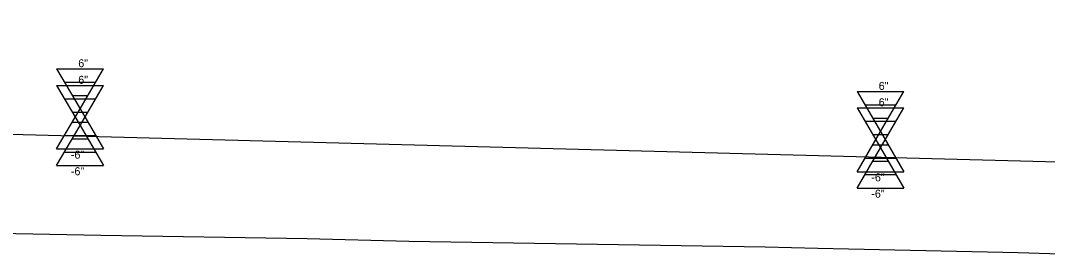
# Model space of a CAD drawing. Extents: x 573468 to 580768, y -57414 to -51768.
# Drawn here: x 574611.5 to 574675.6, y -53062.3 to -53047.5 of the extents above; entities that cross this region are included whole.
import ezdxf

# ---------------------------------------------------------------- set-up
doc = ezdxf.new("R2010")
doc.units = 0
for name, color, linetype in [('Exist Vertical Profile Ground Line', 7, 'Continuous'), ('Pattern 2', 7, 'Continuous'), ('Prop Vertical Profile Grade', 7, 'Continuous'), ('Scratch_Level_0', 7, 'Continuous')]:
    doc.layers.add(name, color=color, linetype=linetype)

msp = doc.modelspace()

# ---------------------------------------------------------------- linework, layer by layer
at = {"layer": 'Exist Vertical Profile Ground Line'}
msp.add_lwpolyline([(574543.255, -53059.77), (574554.026, -53059.906), (574560.775, -53060.086), (574583.28, -53060.379), (574588.793, -53060.537), (574611.208, -53060.826), (574616.517, -53060.941), (574629.403, -53061.136), (574635.759, -53061.316), (574658.007, -53061.658), (574661.307, -53061.757), (574673.813, -53062.023), (574681.74, -53062.264)], dxfattribs=at)
at = {"layer": 'Pattern 2'}
for p, q in [((574613.748, -53051.594), (574616.68, -53051.594)), ((574613.748, -53051.594), (574615.214, -53054.094)), ((574615.214, -53054.094), (574616.68, -53051.594)), ((574614.236, -53052.428), (574616.191, -53052.428)), ((574663.748, -53052.994), (574666.68, -53052.994)), ((574663.748, -53052.994), (574665.214, -53055.494)), ((574665.214, -53055.494), (574666.68, -53052.994)), ((574614.725, -53053.261), (574615.703, -53053.261)), ((574664.236, -53053.828), (574666.191, -53053.828)), ((574613.748, -53056.594), (574615.214, -53054.094)), ((574615.214, -53054.094), (574616.68, -53056.594)), ((574614.725, -53054.928), (574615.703, -53054.928)), ((574664.725, -53054.661), (574665.703, -53054.661)), ((574614.236, -53055.761), (574616.191, -53055.761)), ((574663.748, -53057.994), (574665.214, -53055.494)), ((574665.214, -53055.494), (574666.68, -53057.994)), ((574664.725, -53056.328), (574665.703, -53056.328)), ((574613.748, -53056.594), (574616.68, -53056.594)), ((574664.236, -53057.161), (574666.191, -53057.161)), ((574663.748, -53057.994), (574666.68, -53057.994))]:
    msp.add_line(p, q, dxfattribs=at)
at = {"layer": 'Prop Vertical Profile Grade'}
msp.add_line((574340.214, -53047.545), (574855.214, -53061.042), dxfattribs=at)
at = {"layer": 'Scratch_Level_0'}
for p, q in [((574613.748, -53050.559), (574616.68, -53050.559)), ((574613.748, -53050.559), (574615.214, -53053.059)), ((574615.214, -53053.059), (574616.68, -53050.559)), ((574614.236, -53051.393), (574616.191, -53051.393)), ((574614.725, -53052.226), (574615.703, -53052.226)), ((574663.748, -53051.974), (574666.68, -53051.974)), ((574663.748, -53051.974), (574665.214, -53054.474)), ((574665.214, -53054.474), (574666.68, -53051.974)), ((574613.748, -53055.559), (574615.214, -53053.059)), ((574615.214, -53053.059), (574616.68, -53055.559)), ((574664.236, -53052.808), (574666.191, -53052.808)), ((574664.725, -53053.641), (574665.703, -53053.641)), ((574614.725, -53053.893), (574615.703, -53053.893)), ((574663.748, -53056.974), (574665.214, -53054.474)), ((574665.214, -53054.474), (574666.68, -53056.974)), ((574614.236, -53054.726), (574616.191, -53054.726)), ((574613.748, -53055.559), (574616.68, -53055.559)), ((574664.725, -53055.308), (574665.703, -53055.308)), ((574664.236, -53056.141), (574666.191, -53056.141)), ((574663.748, -53056.974), (574666.68, -53056.974))]:
    msp.add_line(p, q, dxfattribs=at)

# ---------------------------------------------------------------- texts
at = {"layer": 'Pattern 2'}
for s, p in [('6"', (574615.101, -53051.493)), ('6"', (574665.101, -53052.893)), ('-6"', (574614.64, -53057.197)), ('-6"', (574664.64, -53058.597))]:
    msp.add_text(s, height=0.5, rotation=360, dxfattribs=at).set_placement(p)
at = {"layer": 'Scratch_Level_0'}
for s, p in [('6"', (574615.101, -53050.458)), ('6"', (574665.101, -53051.873)), ('-6"', (574614.64, -53056.162)), ('-6"', (574664.64, -53057.577))]:
    msp.add_text(s, height=0.5, dxfattribs=at).set_placement(p)

doc.saveas('drawing.dxf')
